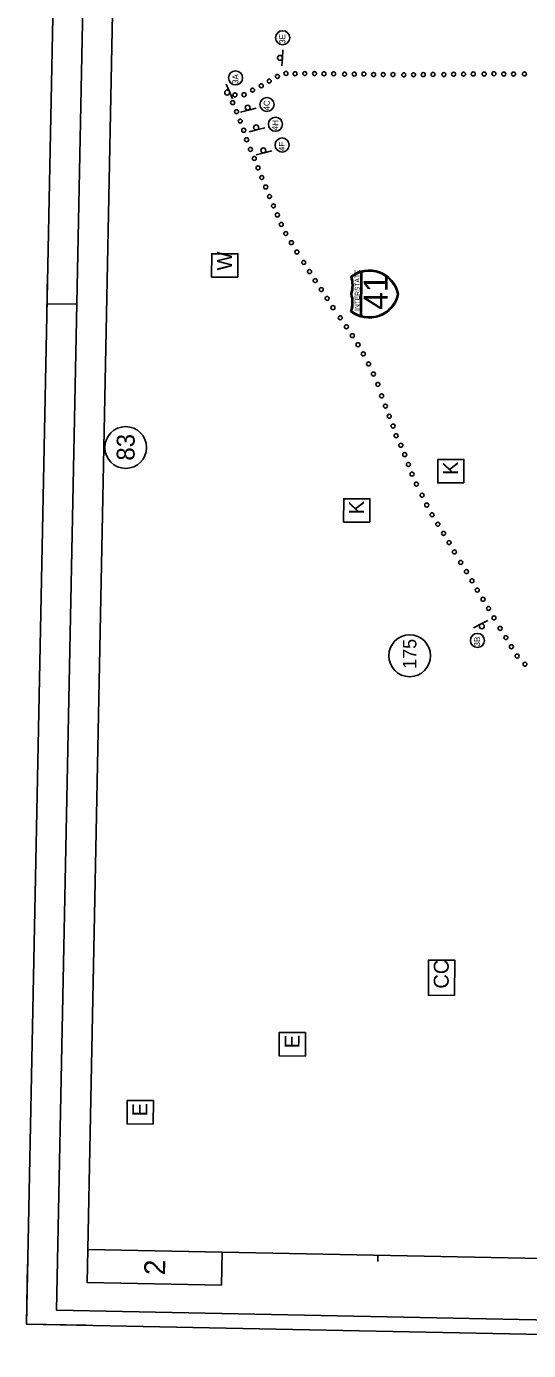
# Model space of a CAD drawing. Extents: x 311409 to 379449, y 121539 to 224848.
# Drawn here: x 311409 to 336594, y 121539 to 187902 of the extents above; entities that cross this region are included whole.
import ezdxf

# ---------------------------------------------------------------- set-up
doc = ezdxf.new("R2010")
doc.units = 0
for name, color, linetype in [('CA-TEXT', 7, 'Continuous'), ('CE-TOPO-CONC-SLAB', 7, 'Continuous'), ('P_RDWY_Text', 7, 'Continuous'), ('PLT_Sheet_Border', 7, 'Continuous'), ('PLT_Sheet_Info', 7, 'Continuous'), ('SIGNS-POLES', 7, 'Continuous')]:
    doc.layers.add(name, color=color, linetype=linetype)

msp = doc.modelspace()

# ---------------------------------------------------------------- linework, layer by layer
at = {"layer": 'CA-TEXT'}
for p, q in [((321337, 175948), (321337, 175948)), ((328176, 175575), (328170, 173406)), ((328220, 173392), (328226, 175590)), ((316386, 166800), (316386, 166800)), ((332681, 165638), (332681, 165638)), ((327962, 163668), (327962, 163668)), ((330631, 156361), (330631, 156361)), ((332214, 140262), (332214, 140262)), ((324730, 136916), (324730, 136916)), ((317101, 133506), (317101, 133506))]:
    msp.add_line(p, q, dxfattribs=at)
for points in [[(322007, 175331), (320695, 175337), (320700, 176514), (322012, 176509)], [(333351, 165022), (332039, 165028), (332044, 166205), (333356, 166200)], [(328633, 163052), (327320, 163058), (327325, 164235), (328637, 164230)], [(332883, 139339), (331571, 139345), (331578, 141111), (332890, 141105)], [(325400, 136300), (324088, 136305), (324093, 137483), (325405, 137477)], [(317772, 132890), (316459, 132895), (316464, 134073), (317776, 134067)]]:
    msp.add_lwpolyline(points, close=True, dxfattribs=at)
for centre, radius in [((324260, 187338), 352), ((321899, 185323), 352), ((323474, 183992), 352), ((323899, 183002), 352), ((324231, 181961), 352), ((316386, 166800), 1048), ((330631, 156361), 1048), ((334028, 157130), 352)]:
    msp.add_circle(centre, radius, dxfattribs=at)
for centre, radius, start, end in [((326240, 174934), 1500, 342.85526, 16.84224), ((328602, 174190), 1500, 11.38318, 128.17727), ((326240, 174934), 1550, 343.41917, 15.55857), ((328602, 174190), 1450, 107.10123, 126.84215), ((328602, 174190), 1450, 11.78677, 105.04344), ((326238, 174058), 1500, 342.85021, 16.83719), ((328604, 174790), 1500, 231.51518, 348.30927), ((326238, 174058), 1550, 344.13388, 16.27328), ((328604, 174790), 1450, 254.64901, 347.90568), ((328604, 174790), 1450, 232.8503, 252.59122)]:
    msp.add_arc(centre, radius, start, end, dxfattribs=at)
at = {"layer": 'CE-TOPO-CONC-SLAB'}
for centre in [(323586, 185161), (323997, 185399), (324427, 185549), (324887, 185534), (325371, 185543), (325859, 185543), (326332, 185529), (326819, 185529), (327366, 185514), (327853, 185514), (328335, 185520), (328822, 185493), (329304, 185493), (329792, 185493), (330338, 185478), (330826, 185482), (331314, 185487), (331802, 185497), (332348, 185494), (332836, 185509), (333334, 185512), (333822, 185522), (334368, 185519), (334856, 185533), (335354, 185518), (335842, 185518), (336389, 185521), (321868, 184472), (322322, 184482), (322748, 184710), (323188, 184930), (321751, 184083), (321946, 183629), (322131, 183158), (322305, 182697), (322451, 182226), (322643, 181741), (322839, 181287), (323023, 180816), (323215, 180330), (323409, 179856), (323602, 179382), (323799, 178911), (323994, 178454), (324192, 177981), (324419, 177523), (324696, 177066), (324972, 176597), (325319, 176073), (325610, 175613), (325891, 175166), (326198, 174717), (326491, 174271), (326783, 173811), (327149, 173300), (327456, 172851), (327752, 172405), (328041, 171952), (328304, 171493), (328567, 170986), (328816, 170483), (329036, 169965), (329226, 169386), (329415, 168875), (329607, 168366), (329799, 167874), (329953, 167391), (330188, 166910), (330383, 166442), (330567, 165951), (330751, 165464), (330966, 164964), (331254, 164407), (331486, 163915), (331756, 163426), (332044, 162956), (332331, 162494), (332608, 162035), (332879, 161563), (333191, 161039), (333478, 160577), (333754, 160118), (334023, 159653), (334311, 159191), (334587, 158732), (334858, 158260), (335170, 157735), (335457, 157273), (335733, 156814), (336019, 156346), (336412, 155939)]:
    msp.add_circle(centre, 100, dxfattribs=at)
at = {"layer": 'P_RDWY_Text'}
msp.add_lwpolyline([(311409, 122868), (313463, 224848), (379449, 223519), (377396, 121539)], close=True, dxfattribs=at)
at = {"layer": 'PLT_Sheet_Border'}
for points in [[(377396, 121539), (379449, 223519), (313463, 224848), (311409, 122868)], [(375910, 122290), (377910, 221569), (314923, 222838), (312923, 123558)]]:
    msp.add_lwpolyline(points, close=True, dxfattribs=at)
at = {"layer": 'PLT_Sheet_Info'}
for p, q in [((314485, 126602), (316388, 221083)), ((312409, 172508), (312469, 175507)), ((312439, 174008), (313939, 173977)), ((374473, 125394), (314485, 126602)), ((329032, 126309), (329026, 126009)), ((311409, 122868), (311469, 125868)), ((314408, 122808), (311409, 122868))]:
    msp.add_line(p, q, dxfattribs=at)
msp.add_lwpolyline([(314485, 126602), (314452, 124953), (321200, 124817), (321233, 126466)], close=True, dxfattribs=at)
at = {"layer": 'SIGNS-POLES'}
for p, q in [((324273, 186735), (324253, 186331)), ((324250, 186328), (324227, 185923)), ((321431, 185016), (321591, 184644)), ((321589, 184640), (321747, 184267)), ((322540, 183713), (322148, 183611)), ((322935, 183815), (322544, 183710)), ((322965, 182723), (322573, 182621)), ((323360, 182825), (322969, 182721)), ((323326, 181572), (322933, 181471)), ((323721, 181673), (323330, 181570)), ((333826, 157767), (334187, 157952)), ((334191, 157951), (334553, 158133))]:
    msp.add_line(p, q, dxfattribs=at)
for centre in [(324126, 186330), (321477, 184588), (322505, 183832), (322930, 182842), (323291, 181691), (334251, 157841)]:
    msp.add_circle(centre, 125, dxfattribs=at)

# ---------------------------------------------------------------- texts
at = {"layer": 'CA-TEXT'}
for s, height, rotation, p in [('3E', 300, 88.84682, (324392, 187032)), ('3A', 300, 88.84682, (322031, 185017)), ('4C', 300, 88.84682, (323605, 183686)), ('4H', 300, 88.84682, (324031, 182696)), ('4F', 300, 88.84682, (324363, 181655)), ('W', 750, 89.76698, (321711, 175669)), ('INTERSTATE', 239.9, 89.84622, (328115, 173651)), ('41', 1199.7, 89.84622, (329527, 173701)), ('83', 900, 89.76698, (316833, 166139)), ('K', 750, 89.76698, (333055, 165424)), ('K', 750, 89.76698, (328336, 163454)), ('3B', 300, 88.84682, (334160, 156824)), ('175', 675, 89.76698, (330965, 155701)), ('CC', 750, 89.76698, (332586, 139676)), ('E', 750, 89.76698, (325104, 136687)), ('E', 750, 89.76698, (317475, 133277))]:
    msp.add_text(s, height=height, rotation=rotation, dxfattribs=at).set_placement(p)
at = {"layer": 'PLT_Sheet_Info'}
msp.add_text('2', height=1050, rotation=88.84622, dxfattribs=at).set_placement((318359, 125306))

doc.saveas('drawing.dxf')
